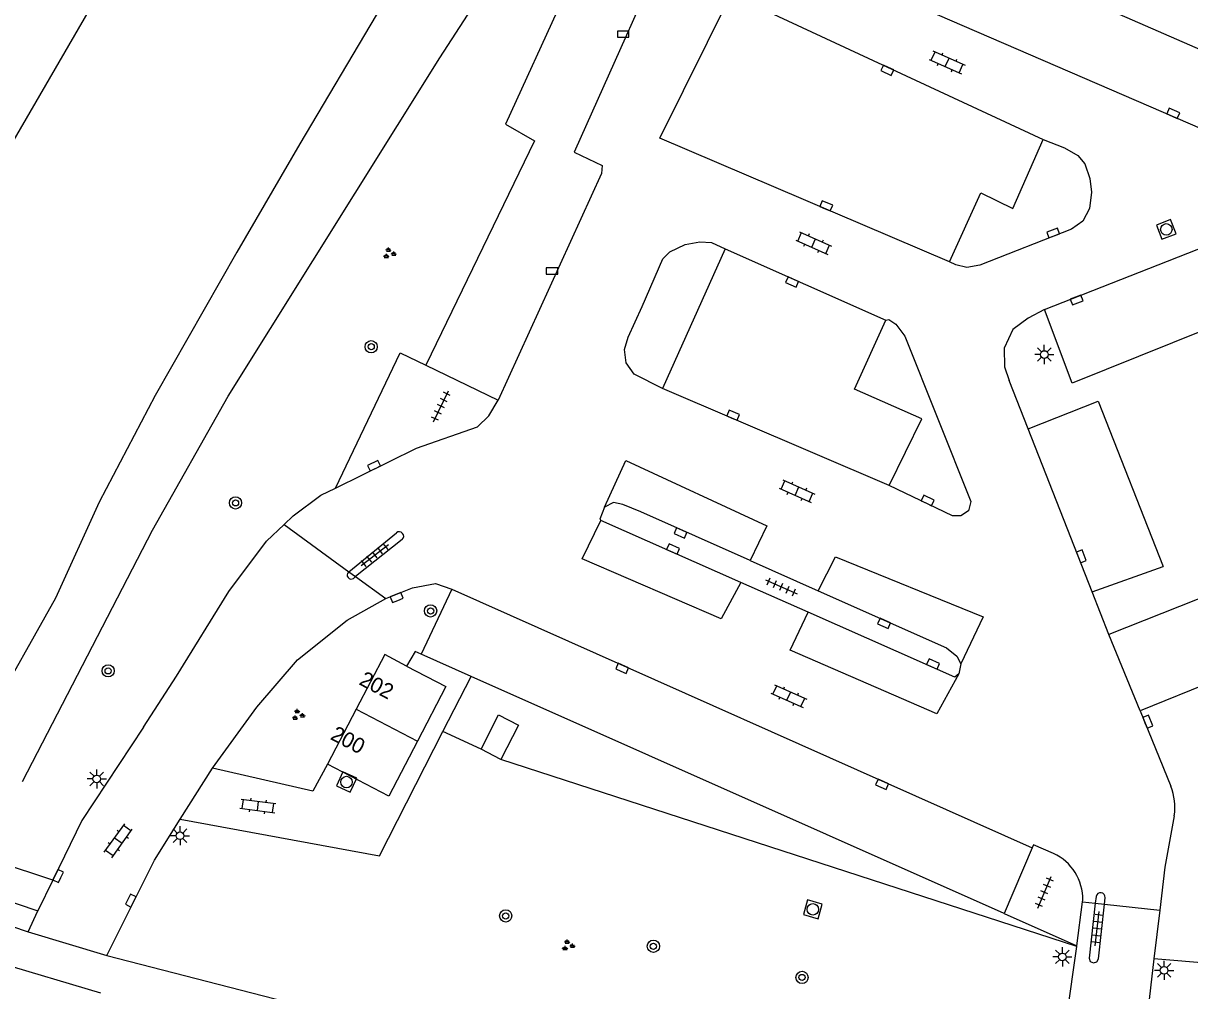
# Model space of a CAD drawing. Extents: x 131000 to 133013, y 393000 to 396501.
# Drawn here: x 131578.2 to 131654.4, y 394802.3 to 394865.5 of the extents above; entities that cross this region are included whole.
import ezdxf

# ---------------------------------------------------------------- set-up
doc = ezdxf.new("R2010")
doc.units = 0
for name, color, linetype in [('gg-afsc-erfafscheiding', 7, 'Continuous'), ('gg-anno-huisnummerreeks BGT', 7, 'Continuous'), ('gg-bbg-bijgebouw', 7, 'Continuous'), ('gg-bbg-hoofdgebouw', 7, 'Continuous'), ('gg-bbg-tussenscheiding', 7, 'Continuous'), ('gg-knt-BGT kruinlijn', 7, 'Continuous'), ('gg-knt-verharding', 7, 'Continuous'), ('gg-knt-verharding nz', 7, 'Continuous'), ('gg-kntw-bovenkant insteek waterloop', 7, 'Continuous'), ('gt-grn-groengrens', 7, 'Continuous'), ('gt-symb-boom', 7, 'Continuous'), ('gt-symb-groenvak', 7, 'Continuous'), ('gt-symb-klinker verharding', 7, 'Continuous'), ('gt-symb-kolk', 7, 'Continuous'), ('gt-symb-lichtmast', 7, 'Continuous'), ('gt-symb-rioolschacht', 7, 'Continuous'), ('gt-symb-tegel verharding', 7, 'Continuous')]:
    doc.layers.add(name, color=color, linetype=linetype)

# ---------------------------------------------------------------- blocks, each defined once
blk = doc.blocks.new('gt0-KOLK')
at = {"layer": 'gt-symb-kolk'}
blk.add_lwpolyline([(0, 0), (0.375, 0), (0.375, 0.4), (-0.375, 0.4), (-0.375, 0), (0, 0)], dxfattribs=at)
blk = doc.blocks.new('gt0-LMAST')
at = {"layer": 'gt-symb-lichtmast'}
for p, q in [((-0.182, 0.173), (-0.447, 0.438)), ((-0.005, 0.246), (-0.005, 0.621)), ((0.172, 0.173), (0.437, 0.438)), ((-0.255, -0.004), (-0.63, -0.004)), ((-0.182, -0.181), (-0.447, -0.446)), ((-0.005, -0.254), (-0.005, -0.629)), ((0.437, -0.446), (0.172, -0.181)), ((0.245, -0.004), (0.62, -0.004))]:
    blk.add_line(p, q, dxfattribs=at)
blk.add_circle((-0.005, -0.004), 0.25, dxfattribs=at)
blk = doc.blocks.new('gt0-TEG1')
at = {"layer": 'gt-symb-tegel verharding'}
for p, q in [((-1.125, 0), (1.125, 0)), ((-0.9, -0.25), (-0.9, 0.25)), ((-0.45, -0.25), (-0.45, 0.25)), ((0, -0.25), (0, 0.25)), ((0.45, -0.25), (0.45, 0.25)), ((0.9, -0.25), (0.9, 0.25))]:
    blk.add_line(p, q, dxfattribs=at)
blk = doc.blocks.new('gt0-RS')
at = {"layer": 'gt-symb-rioolschacht'}
blk.add_lwpolyline([(-0.5, -0.5), (0.5, -0.5), (0.5, 0.5), (-0.5, 0.5)], close=True, dxfattribs=at)
blk.add_circle((0, 0), 0.375, dxfattribs=at)
blk = doc.blocks.new('gt0-KL1')
at = {"layer": 'gt-symb-klinker verharding'}
for p, q in [((-1.15, 0.3), (1.15, 0.3)), ((-1, -0.3), (-1, 0.3)), ((-0.5, 0.3), (-0.5, 0.45)), ((0, -0.3), (0, 0.3)), ((0.5, 0.3), (0.5, 0.45)), ((1, -0.3), (1, 0.3)), ((-1.15, -0.3), (1.15, -0.3)), ((-0.5, -0.45), (-0.5, -0.3)), ((0.5, -0.45), (0.5, -0.3))]:
    blk.add_line(p, q, dxfattribs=at)
blk = doc.blocks.new('gt0-BOOM')
at = {"layer": 'gt-symb-boom'}
for radius in [0.4, 0.2]:
    blk.add_circle((0, 0), radius, dxfattribs=at)
blk = doc.blocks.new('gt0-GRVAK')
at = {"layer": 'gt-symb-groenvak'}
for p, q in [((-0.11, 0.189), (-0.228, 0.24)), ((-0.182, 0.153), (0.088, 0.153)), ((-0.091, 0.211), (-0.156, 0.322)), ((-0.047, 0.214), (-0.047, 0.393)), ((-0.004, 0.211), (0.061, 0.322)), ((0.015, 0.189), (0.133, 0.24)), ((0.262, -0.052), (0.197, 0.059)), ((0.305, -0.049), (0.305, 0.13)), ((0.349, -0.052), (0.414, 0.059)), ((-0.245, -0.228), (-0.363, -0.177)), ((-0.318, -0.264), (-0.047, -0.264)), ((-0.226, -0.206), (-0.291, -0.095)), ((-0.183, -0.203), (-0.183, -0.024)), ((-0.139, -0.206), (-0.074, -0.095)), ((-0.12, -0.228), (-0.002, -0.177)), ((0.243, -0.074), (0.125, -0.023)), ((0.17, -0.11), (0.441, -0.11)), ((0.368, -0.074), (0.486, -0.023))]:
    blk.add_line(p, q, dxfattribs=at)

msp = doc.modelspace()

# ---------------------------------------------------------------- linework, layer by layer
at = {"layer": 'gg-afsc-erfafscheiding'}
for p, q in [((131595.245, 394832.72), (131599.471, 394829.637)), ((131599.471, 394829.637), (131599.912, 394829.316)), ((131599.912, 394829.316), (131601.885, 394827.876)), ((131647.386, 394808.075), (131648.21, 394807.985)), ((131648.21, 394807.985), (131648.809, 394807.92)), ((131648.809, 394807.92), (131652.417, 394807.528))]:
    msp.add_line(p, q, dxfattribs=at)
at = {"layer": 'gg-bbg-bijgebouw'}
msp.add_line((131609.4, 394817.37), (131608.1, 394818.04), dxfattribs=at)
msp.add_lwpolyline([(131608.1, 394818.04), (131609.25, 394820.28), (131610.55, 394819.61), (131609.4, 394817.37)], dxfattribs=at)
at = {"layer": 'gg-bbg-hoofdgebouw'}
msp.add_line((131599.955, 394820.66), (131598.08, 394817.06), dxfattribs=at)
for points in [[(131603.233, 394823.476), (131601.81, 394824.22), (131599.955, 394820.66)], [(131603.233, 394823.476), (131605.81, 394822.13), (131603.948, 394818.566)], [(131603.948, 394818.566), (131602.07, 394814.97), (131598.08, 394817.06)]]:
    msp.add_lwpolyline(points, dxfattribs=at)
at = {"layer": 'gg-bbg-tussenscheiding'}
msp.add_line((131599.955, 394820.66), (131603.948, 394818.566), dxfattribs=at)
at = {"layer": 'gg-knt-BGT kruinlijn'}
msp.add_lwpolyline([(131558.065, 394827.35), (131560.82, 394826.86), (131567.27, 394840.06), (131584.09, 394869.05), (131602.98, 394898.27), (131615.298, 394914.196)], dxfattribs=at)
at = {"layer": 'gg-knt-verharding'}
for p, q in [((131624.046, 394850.712), (131619.944, 394841.6)), ((131604.491, 394843.121), (131609.218, 394840.849)), ((131643.823, 394838.957), (131642.58, 394842.12)), ((131625.071, 394828.937), (131615.925, 394832.982)), ((131599.471, 394829.637), (131602.576, 394832.18)), ((131602.958, 394831.738), (131599.912, 394829.316)), ((131625.677, 394830.367), (131630.119, 394828.394)), ((131648.006, 394828.315), (131652.636, 394829.977)), ((131599.435, 394829.608), (131599.471, 394829.637)), ((131599.912, 394829.316), (131599.766, 394829.2)), ((131606.198, 394828.488), (131604.18, 394824.251)), ((131629.457, 394826.996), (131625.071, 394828.937)), ((131649.098, 394825.537), (131648.006, 394828.315)), ((131651.136, 394820.54), (131649.098, 394825.537)), ((131663.537, 394825.612), (131651.136, 394820.54)), ((131607.448, 394822.797), (131604.18, 394824.251)), ((131639.427, 394823.628), (131639.289, 394822.964)), ((131605.613, 394819.209), (131607.448, 394822.797)), ((131642.26, 394807.31), (131607.448, 394822.797)), ((131651.136, 394820.54), (131653.139, 394815.63)), ((131653.37, 394813.685), (131652.75, 394810.34)), ((131580.14, 394809.5), (131575.514, 394811.022)), ((131644.091, 394811.605), (131642.26, 394807.31)), ((131652.75, 394810.34), (131652.417, 394807.528)), ((131572.669, 394809.664), (131579.16, 394807.49)), ((131580.14, 394809.5), (131579.16, 394807.49)), ((131647.012, 394805.196), (131647.386, 394808.075)), ((131647.386, 394808.075), (131647.4, 394808.18)), ((131648.259, 394808.428), (131648.21, 394807.985)), ((131648.809, 394807.92), (131648.855, 394808.343)), ((131578.536, 394806.119), (131579.16, 394807.49)), ((131642.26, 394807.31), (131647.012, 394805.196)), ((131652.417, 394807.528), (131652.04, 394804.349)), ((131578.536, 394806.119), (131583.654, 394804.563)), ((131645.44, 394794.183), (131647.007, 394805.16)), ((131647.007, 394805.16), (131647.012, 394805.196)), ((131575.943, 394804.308), (131583.248, 394802.138)), ((131652.04, 394804.349), (131651.583, 394800.488))]:
    msp.add_line(p, q, dxfattribs=at)
for points in [[(131657.004, 394857.746), (131658.635, 394862.179), (131623.632, 394877.466), (131621.285, 394873.374), (131617.152, 394875.162), (131609.69, 394858.859), (131611.583, 394857.779), (131604.491, 394843.121)], [(131644.8, 394857.862), (131646.19, 394857.309), (131647.061, 394856.823), (131647.526, 394856.277), (131647.849, 394855.323), (131647.967, 394854.416), (131647.837, 394853.347), (131647.399, 394852.528), (131646.651, 394852.008), (131640.677, 394849.664), (131639.821, 394849.493), (131639.109, 394849.68), (131638.699, 394849.873)], [(131638.699, 394849.873), (131640.735, 394854.37), (131642.83, 394853.351), (131644.8, 394857.862)], [(131657.931, 394851.887), (131659.795, 394847.222), (131646.697, 394841.952), (131644.883, 394846.765)], [(131619.944, 394841.6), (131618.108, 394842.535), (131617.587, 394843.283), (131617.47, 394844.142), (131617.706, 394844.957), (131618.627, 394846.948), (131619.981, 394850.061), (131620.427, 394850.526), (131621.429, 394851.002), (131622.387, 394851.172), (131623.146, 394851.137), (131624.046, 394850.712)], [(131644.883, 394846.765), (131643.832, 394846.187), (131642.834, 394845.46), (131642.252, 394844.235), (131642.277, 394843.022), (131642.58, 394842.12)], [(131634.743, 394835.272), (131636.883, 394839.618), (131632.493, 394841.554), (131634.541, 394846.066)], [(131634.541, 394846.066), (131634.729, 394846.103), (131635.19, 394845.809), (131635.763, 394845.009), (131640.075, 394834.216), (131639.937, 394833.607), (131639.437, 394833.291), (131638.881, 394833.279), (131634.743, 394835.272)], [(131598.587, 394835.101), (131602.823, 394843.922), (131604.491, 394843.121)], [(131598.587, 394835.101), (131603.89, 394837.695), (131607.858, 394839.091), (131608.602, 394839.816), (131609.218, 394840.849)], [(131643.823, 394838.957), (131648.39, 394840.768), (131652.636, 394829.977)], [(131595.245, 394832.72), (131595.835, 394833.283), (131597.629, 394834.633), (131598.587, 394835.101)], [(131616.158, 394833.84), (131615.863, 394833.071), (131615.925, 394832.982)], [(131625.677, 394830.367), (131618.542, 394833.535), (131617.368, 394834.017), (131616.759, 394834.156), (131616.158, 394833.84)], [(131586.05, 394819.49), (131588.205, 394822.805), (131591.634, 394828.34), (131594.099, 394831.625), (131595.245, 394832.72)], [(131664.53, 394828.4), (131660.73, 394830.16), (131649.098, 394825.537)], [(131601.885, 394827.876), (131603.617, 394828.589), (131605.128, 394828.871), (131606.198, 394828.488)], [(131630.119, 394828.394), (131638.495, 394824.674), (131639.164, 394824.13), (131639.427, 394823.628)], [(131590.56, 394816.8), (131593.454, 394820.791), (131596.124, 394823.878), (131599.359, 394826.478), (131601.885, 394827.876)], [(131639.289, 394822.964), (131639.04, 394822.757), (131629.457, 394826.996)], [(131604.18, 394824.251), (131603.8, 394824.42), (131603.233, 394823.476)], [(131586.05, 394819.49), (131582.03, 394813.38), (131580.14, 394809.5)], [(131588.45, 394813.47), (131601.46, 394811.09), (131605.613, 394819.209)], [(131598.08, 394817.06), (131597.12, 394815.3), (131590.56, 394816.8)], [(131552.191, 394815.965), (131563.333, 394811.545), (131571.725, 394808.425), (131578.536, 394806.119)], [(131583.654, 394804.563), (131586.77, 394810.8), (131588.45, 394813.47)], [(131645.49, 394811.24), (131644.17, 394811.79), (131644.091, 394811.605)], [(131648.21, 394807.985), (131647.808, 394804.392), (131647.886, 394804.187), (131648.085, 394804.092), (131648.319, 394804.157), (131648.423, 394804.345), (131648.809, 394807.92)], [(131583.654, 394804.563), (131595.322, 394801.574), (131604.772, 394799.448), (131614.956, 394797.663), (131623.89, 394796.421), (131625.872, 394796.195)]]:
    msp.add_lwpolyline(points, dxfattribs=at)
for centre, radius, start, end in [((131602.756, 394831.949), 0.292, 313.69097, 127.97968), ((131599.62, 394829.42), 0.264, 134.56409, 303.53899), ((131649.611, 394814.225), 3.798, 351.82985, 21.71629), ((131644.069, 394808.227), 3.331, 359.18899, 64.75443), ((131648.555, 394808.373), 0.301, 354.32986, 169.43685)]:
    msp.add_arc(centre, radius, start, end, dxfattribs=at)
at = {"layer": 'gg-knt-verharding nz'}
for p, q in [((131644.883, 394846.765), (131657.931, 394851.887)), ((131624.046, 394850.712), (131634.541, 394846.066)), ((131634.743, 394835.272), (131619.944, 394841.6)), ((131648.006, 394828.315), (131643.823, 394838.957)), ((131606.198, 394828.488), (131644.091, 394811.605)), ((131588.45, 394813.47), (131590.56, 394816.8))]:
    msp.add_line(p, q, dxfattribs=at)
for points in [[(131657.004, 394857.746), (131621.391, 394873.168), (131614.178, 394857.025), (131616.015, 394856.156), (131615.975, 394855.65), (131609.218, 394840.849)], [(131638.699, 394849.873), (131619.774, 394857.951), (131624.441, 394867.356), (131644.8, 394857.862)], [(131616.158, 394833.84), (131617.563, 394836.907), (131626.753, 394832.634), (131625.677, 394830.367)], [(131625.071, 394828.937), (131623.789, 394826.555), (131614.707, 394830.473), (131615.925, 394832.982)], [(131630.119, 394828.394), (131631.245, 394830.597), (131640.884, 394826.689), (131639.427, 394823.628)], [(131639.289, 394822.964), (131637.873, 394820.358), (131628.281, 394824.518), (131629.457, 394826.996)]]:
    msp.add_lwpolyline(points, dxfattribs=at)
at = {"layer": 'gg-kntw-bovenkant insteek waterloop'}
for points in [[(131628.58, 394903.166), (131623.057, 394896.212), (131616.11, 394886.915), (131613.84, 394884.087), (131611.584, 394880.503), (131606.955, 394874.287), (131601.253, 394865.974), (131596.261, 394857.577), (131592.153, 394850.513), (131586.828, 394841.143), (131583.173, 394834.185), (131580.314, 394827.901), (131575.918, 394820.124), (131574.799, 394818.004)], [(131578.165, 394815.923), (131586.649, 394832.339), (131591.582, 394841.09), (131605.403, 394863.189), (131612.96, 394874.873), (131617.887, 394881.494), (131619.601, 394884.266), (131632.488, 394900.107)]]:
    msp.add_lwpolyline(points, dxfattribs=at)
at = {"layer": 'gt-grn-groengrens'}
for p, q in [((131608.1, 394818.04), (131605.613, 394819.209)), ((131647.007, 394805.16), (131609.4, 394817.37))]:
    msp.add_line(p, q, dxfattribs=at)
msp.add_lwpolyline([(131696.839, 394802.321), (131674.107, 394802.503), (131652.04, 394804.349)], dxfattribs=at)

# ---------------------------------------------------------------- block references
at = {"layer": 'gt-symb-boom'}
for p in [(131600.927, 394844.331), (131592.068, 394834.127), (131604.807, 394827.073), (131583.75, 394823.16), (131609.709, 394807.153), (131619.354, 394805.171), (131629.06, 394803.139)]:
    msp.add_blockref('gt0-BOOM', p, dxfattribs=at)
at = {"layer": 'gt-symb-groenvak'}
for p in [(131602.101, 394850.421), (131596.141, 394820.277), (131613.768, 394805.219)]:
    msp.add_blockref('gt0-GRVAK', p, dxfattribs=at)
at = {"layer": 'gt-symb-klinker verharding'}
for p, rotation in [((131638.536, 394862.902), -23.950855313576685), ((131629.818, 394851.1), -23.95085531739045), ((131628.731, 394834.897), -23.950855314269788), ((131628.198, 394821.512), -23.95085531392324), ((131593.532, 394814.335), -7.295560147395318), ((131584.412, 394812.069), 54.448991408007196)]:
    msp.add_blockref('gt0-KL1', p, dxfattribs=dict(at, rotation=rotation))
at = {"layer": 'gt-symb-kolk'}
for p in [(131617.384, 394864.546), (131612.738, 394849.074)]:
    msp.add_blockref('gt0-KOLK', p, dxfattribs=at)
for p, rotation in [((131634.716, 394862.568), 155.1768596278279), ((131653.223, 394859.384), -23.386642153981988), ((131630.563, 394853.345), -23.20611458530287), ((131645.533, 394851.568), 21.461063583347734), ((131628.492, 394848.744), 156.17710050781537), ((131646.916, 394847.564), -158.77323173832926), ((131624.487, 394839.673), -22.82254064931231), ((131601.202, 394836.383), 26.10382498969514), ((131637.182, 394834.103), -25.719512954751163), ((131621.206, 394832.35), 155.97349342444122), ((131620.563, 394830.929), -23.56707121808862), ((131647.116, 394830.572), -68.64562263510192), ((131602.658, 394827.761), 22.152586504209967), ((131634.5, 394826.445), 156.22952419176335), ((131637.532, 394823.423), -24.0265065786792), ((131617.234, 394823.134), -23.89847787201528), ((131651.449, 394819.762), -67.48588735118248), ((131634.37, 394815.937), 156.17710051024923), ((131580.665, 394809.673), 63.84474624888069), ((131585.402, 394808.065), 62.486938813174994)]:
    msp.add_blockref('gt0-KOLK', p, dxfattribs=dict(at, rotation=rotation))
at = {"layer": 'gt-symb-lichtmast'}
for p in [(131644.886, 394843.824), (131583.012, 394816.105), (131588.448, 394812.395), (131646.067, 394804.485), (131652.711, 394803.604)]:
    msp.add_blockref('gt0-LMAST', p, dxfattribs=at)
at = {"layer": 'gt-symb-rioolschacht'}
for p, rotation in [((131652.848, 394851.992), 21.46106358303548), ((131599.318, 394815.897), -114.82314037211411), ((131629.769, 394807.585), 74.33789365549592)]:
    msp.add_blockref('gt0-RS', p, dxfattribs=dict(at, rotation=rotation))
at = {"layer": 'gt-symb-tegel verharding'}
for p, rotation in [((131605.478, 394840.442), 64.3321248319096), ((131601.161, 394830.732), 37.89006280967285), ((131627.71, 394828.649), -23.950855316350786), ((131644.892, 394808.69), 66.92177859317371), ((131648.335, 394806.319), 83.10945167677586)]:
    msp.add_blockref('gt0-TEG1', p, dxfattribs=dict(at, rotation=rotation))

# ---------------------------------------------------------------- texts
at = {"layer": 'gg-anno-huisnummerreeks BGT'}
for s, p in [('202', (131600.071, 394822.301)), ('200', (131598.202, 394818.723))]:
    msp.add_text(s, height=1, rotation=332.4, dxfattribs=at).set_placement(p)

doc.saveas('drawing.dxf')
